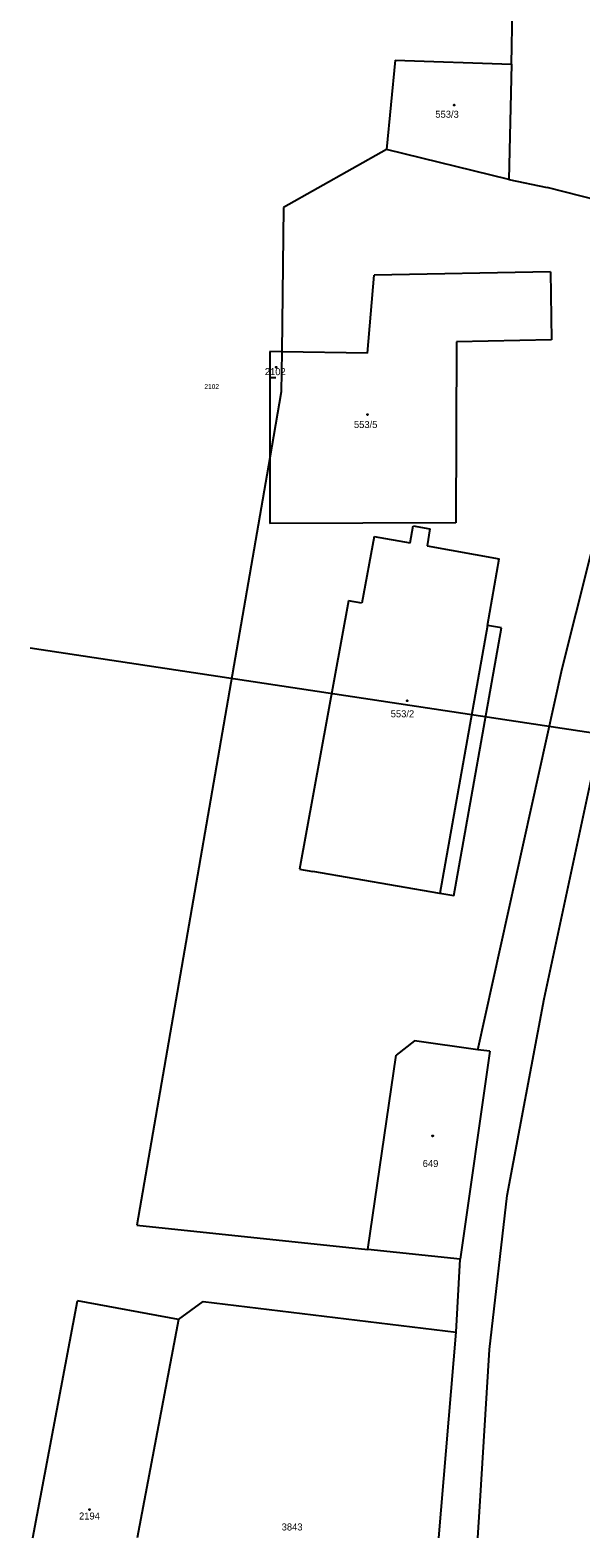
# Model space of a CAD drawing. Extents: x -866624 to -866276, y -1050208 to -1049940.
# Drawn here: x -866507.6 to -866468.3, y -1050208.1 to -1050100.7 of the extents above; entities that cross this region are included whole.
import ezdxf

# ---------------------------------------------------------------- set-up
doc = ezdxf.new("R2010")
doc.units = 0
for name, color, linetype in [('_FORMATY', 7, 'Continuous'), ('Default', 7, 'Continuous'), ('Hranice', 7, 'Continuous'), ('Hranice další', 7, 'Continuous'), ('Hranice-budov', 7, 'Continuous'), ('Parcela-pozemkova', 7, 'Continuous'), ('Parcela-stavebni', 7, 'Continuous'), ('Parcelni-cisla-pomocna', 7, 'Continuous'), ('znacky-budov', 7, 'Continuous')]:
    doc.layers.add(name, color=color, linetype=linetype)

# ---------------------------------------------------------------- blocks, each defined once
blk = doc.blocks.new('s_zdena')
at = {"layer": 'Default'}
blk.add_circle((0, 0), 0.175, dxfattribs=at)
for start, end in [(0, 180), (180, 0)]:
    blk.add_arc((0, 0), 0.0875, start, end, dxfattribs=at)

msp = doc.modelspace()

# ---------------------------------------------------------------- linework, layer by layer
at = {"layer": '_FORMATY'}
msp.add_line((-866507.55, -1050144.69), (-866448.82, -1050153.56), dxfattribs=at)
at = {"layer": 'Hranice'}
for p, q in [((-866473.26, -1050103.09), (-866473.17, -1050099.15)), ((-866481.54, -1050102.8), (-866482.16, -1050109.18)), ((-866481.54, -1050102.8), (-866473.26, -1050103.09)), ((-866473.26, -1050103.09), (-866473.45, -1050111.3)), ((-866482.16, -1050109.18), (-866489.5, -1050113.31)), ((-866473.45, -1050111.3), (-866482.16, -1050109.18)), ((-866473.45, -1050111.3), (-866470.72, -1050111.89)), ((-866463.4, -1050113.74), (-866470.72, -1050111.89)), ((-866489.5, -1050113.31), (-866489.63, -1050123.59)), ((-866483.51, -1050123.69), (-866483.03, -1050118.14)), ((-866470.47, -1050117.89), (-866483.03, -1050118.14)), ((-866470.47, -1050117.89), (-866470.41, -1050122.74)), ((-866477.18, -1050122.88), (-866477.21, -1050135.78)), ((-866470.41, -1050122.74), (-866477.18, -1050122.88)), ((-866490.47, -1050123.58), (-866490.48, -1050131.16)), ((-866489.63, -1050123.59), (-866490.47, -1050123.58)), ((-866489.63, -1050123.59), (-866489.66, -1050126.44)), ((-866483.51, -1050123.69), (-866489.63, -1050123.59)), ((-866489.66, -1050126.44), (-866490.48, -1050131.16)), ((-866490.48, -1050131.16), (-866499.94, -1050185.85)), ((-866490.48, -1050131.16), (-866490.48, -1050135.83)), ((-866470.92, -1050169.71), (-866463.14, -1050133.28)), ((-866469.64, -1050146.17), (-866466.62, -1050134.17)), ((-866477.21, -1050135.78), (-866490.48, -1050135.83)), ((-866475.65, -1050173.36), (-866469.64, -1050146.17)), ((-866473.56, -1050183.73), (-866470.92, -1050169.71)), ((-866480.17, -1050172.72), (-866481.46, -1050173.74)), ((-866475.65, -1050173.36), (-866480.17, -1050172.72)), ((-866474.8, -1050173.45), (-866476.9, -1050188.27)), ((-866474.8, -1050173.45), (-866475.65, -1050173.36)), ((-866483.49, -1050187.58), (-866481.46, -1050173.74)), ((-866474.82, -1050194.73), (-866473.56, -1050183.73)), ((-866499.94, -1050185.85), (-866483.49, -1050187.58)), ((-866476.9, -1050188.27), (-866483.49, -1050187.58)), ((-866477.19, -1050193.48), (-866476.9, -1050188.27)), ((-866507.36, -1050208.15), (-866504.19, -1050191.24)), ((-866496.99, -1050192.59), (-866504.19, -1050191.24)), ((-866496.99, -1050192.59), (-866495.23, -1050191.3)), ((-866495.23, -1050191.3), (-866477.19, -1050193.48)), ((-866496.99, -1050192.59), (-866499.92, -1050208.15)), ((-866478.43, -1050208.15), (-866477.19, -1050193.48)), ((-866475.52, -1050205.91), (-866474.82, -1050194.73)), ((-866475.64, -1050208.15), (-866475.52, -1050205.91))]:
    msp.add_line(p, q, dxfattribs=at)
at = {"layer": 'Hranice další'}
for p, q in [((-866483.04, -1050136.76), (-866483.91, -1050141.52)), ((-866483.04, -1050136.76), (-866480.47, -1050137.22)), ((-866480.47, -1050137.22), (-866480.25, -1050136.01)), ((-866480.25, -1050136.01), (-866479.06, -1050136.22)), ((-866479.06, -1050136.22), (-866479.27, -1050137.43)), ((-866479.27, -1050137.43), (-866474.12, -1050138.35)), ((-866474.96, -1050143.1), (-866474.12, -1050138.35)), ((-866484.86, -1050141.34), (-866488.37, -1050160.47)), ((-866483.91, -1050141.52), (-866484.86, -1050141.34)), ((-866474.96, -1050143.1), (-866478.35, -1050162.2)), ((-866477.36, -1050162.38), (-866473.97, -1050143.28)), ((-866473.97, -1050143.28), (-866474.96, -1050143.1)), ((-866488.37, -1050160.47), (-866487.42, -1050160.64)), ((-866478.35, -1050162.2), (-866487.42, -1050160.64)), ((-866477.36, -1050162.38), (-866478.35, -1050162.2))]:
    msp.add_line(p, q, dxfattribs=at)
at = {"layer": 'Hranice-budov'}
for p, q in [((-866481.54, -1050102.8), (-866482.16, -1050109.18)), ((-866481.54, -1050102.8), (-866473.26, -1050103.09)), ((-866473.26, -1050103.09), (-866473.45, -1050111.3)), ((-866473.45, -1050111.3), (-866482.16, -1050109.18)), ((-866483.51, -1050123.69), (-866483.03, -1050118.14)), ((-866470.47, -1050117.89), (-866483.03, -1050118.14)), ((-866470.47, -1050117.89), (-866470.41, -1050122.74)), ((-866477.18, -1050122.88), (-866477.21, -1050135.78)), ((-866470.41, -1050122.74), (-866477.18, -1050122.88)), ((-866490.47, -1050123.58), (-866490.48, -1050131.16)), ((-866489.63, -1050123.59), (-866490.47, -1050123.58)), ((-866483.51, -1050123.69), (-866489.63, -1050123.59)), ((-866490.48, -1050131.16), (-866490.48, -1050135.83)), ((-866477.21, -1050135.78), (-866490.48, -1050135.83)), ((-866483.04, -1050136.76), (-866483.91, -1050141.52)), ((-866483.04, -1050136.76), (-866480.47, -1050137.22)), ((-866480.47, -1050137.22), (-866480.25, -1050136.01)), ((-866480.25, -1050136.01), (-866479.06, -1050136.22)), ((-866479.06, -1050136.22), (-866479.27, -1050137.43)), ((-866479.27, -1050137.43), (-866474.12, -1050138.35)), ((-866474.96, -1050143.1), (-866474.12, -1050138.35)), ((-866484.86, -1050141.34), (-866488.37, -1050160.47)), ((-866483.91, -1050141.52), (-866484.86, -1050141.34)), ((-866474.96, -1050143.1), (-866478.35, -1050162.2)), ((-866488.37, -1050160.47), (-866487.42, -1050160.64)), ((-866478.35, -1050162.2), (-866487.42, -1050160.64)), ((-866480.17, -1050172.72), (-866481.46, -1050173.74)), ((-866475.65, -1050173.36), (-866480.17, -1050172.72)), ((-866474.8, -1050173.45), (-866476.9, -1050188.27)), ((-866474.8, -1050173.45), (-866475.65, -1050173.36)), ((-866483.49, -1050187.58), (-866481.46, -1050173.74)), ((-866476.9, -1050188.27), (-866483.49, -1050187.58)), ((-866507.36, -1050208.15), (-866504.19, -1050191.24)), ((-866496.99, -1050192.59), (-866504.19, -1050191.24)), ((-866496.99, -1050192.59), (-866499.92, -1050208.15))]:
    msp.add_line(p, q, dxfattribs=at)
at = {"layer": 'Parcelni-cisla-pomocna'}
msp.add_line((-866490.45, -1050125.43), (-866490.05, -1050125.43), dxfattribs=at)

# ---------------------------------------------------------------- block references
at = {"layer": 'znacky-budov', "xscale": 0.2, "yscale": 0.20000000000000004}
for p in [(-866477.34, -1050106.01), (-866490.03, -1050124.7), (-866483.51, -1050128.07), (-866480.69, -1050148.47), (-866478.87, -1050179.49), (-866503.32, -1050206.13)]:
    msp.add_blockref('s_zdena', p, dxfattribs=at)

# ---------------------------------------------------------------- texts
at = {"layer": 'Parcela-pozemkova'}
msp.add_text('3843', height=0.5, dxfattribs=at).set_placement((-866489.63, -1050207.62))
at = {"layer": 'Parcela-stavebni'}
for s, p in [('553/3', (-866478.68, -1050106.91)), ('2102', (-866490.83, -1050125.26)), ('553/5', (-866484.48, -1050129.03)), ('553/2', (-866481.86, -1050149.65)), ('649', (-866479.58, -1050181.71)), ('2194', (-866504.07, -1050206.84))]:
    msp.add_text(s, height=0.5, dxfattribs=at).set_placement(p)
at = {"layer": 'Parcelni-cisla-pomocna'}
msp.add_text('2102', height=0.34, dxfattribs=at).set_placement((-866495.14, -1050126.24))

doc.saveas('drawing.dxf')
